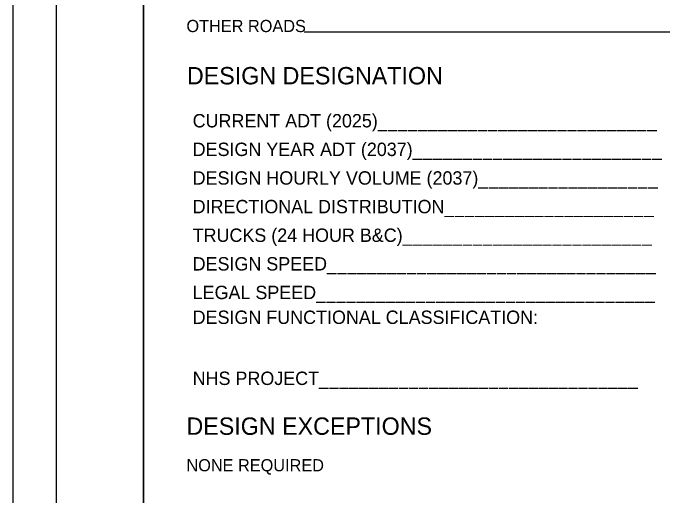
# Model space of a CAD drawing. Extents: x 0 to 34, y 0 to 22.
# Drawn here: x 0 to 7.46, y 5.55 to 11.1 of the extents above; entities that cross this region are included whole.
import ezdxf

# ---------------------------------------------------------------- set-up
doc = ezdxf.new("R2010")
doc.units = 0
for name, color, linetype in [('SH_Border', 7, 'Continuous'), ('SH_Cut_Line', 7, 'Continuous'), ('SH_Data', 7, 'Continuous'), ('SH_Text', 7, 'Continuous')]:
    doc.layers.add(name, color=color, linetype=linetype)

msp = doc.modelspace()

# ---------------------------------------------------------------- linework, layer by layer
at = {"layer": 'SH_Border'}
for points in [[(0.5, 21.5), (1.5, 21.5), (1.5, 0.5), (0.5, 0.5)], [(1.5, 21.5), (33.5, 21.5), (33.5, 0.5), (1.5, 0.5)]]:
    msp.add_lwpolyline(points, close=True, dxfattribs=at)
at = {"layer": 'SH_Cut_Line'}
msp.add_lwpolyline([(0, 0), (34, 0), (34, 22), (0, 22)], close=True, dxfattribs=at)
at = {"layer": 'SH_Data'}
msp.add_line((7.7, 10.8767), (3.3471, 10.8767), dxfattribs=at)

# ---------------------------------------------------------------- texts
msp.add_text('DESIGN DESIGNATION', height=0.2, dxfattribs=at).set_placement((2, 10.2747))
at = {"layer": 'SH_Text'}
for s, height, p in [('OTHER ROADS', 0.14, (1.9944, 10.8767)), ('CURRENT ADT (2025)____________________________', 0.154, (2.0659, 9.7795)), ('DESIGN YEAR ADT (2037)_________________________', 0.154, (2.0659, 9.4501)), ('DESIGN HOURLY VOLUME (2037)__________________', 0.154, (2.0659, 9.1207)), ('DIRECTIONAL DISTRIBUTION_____________________', 0.154, (2.0659, 8.7913)), ('TRUCKS (24 HOUR B&C)_________________________', 0.154, (2.0659, 8.4619)), ('DESIGN SPEED_________________________________', 0.154, (2.0659, 8.1324)), ('LEGAL SPEED__________________________________', 0.154, (2.0659, 7.803)), ('DESIGN FUNCTIONAL CLASSIFICATION:', 0.154, (2.0659, 7.5173)), ('NHS PROJECT________________________________', 0.154, (2.0659, 6.8148)), ('DESIGN EXCEPTIONS', 0.2, (1.9944, 6.2413)), ('NONE REQUIRED', 0.14, (1.9944, 5.8213))]:
    msp.add_text(s, height=height, dxfattribs=at).set_placement(p)

doc.saveas('drawing.dxf')
